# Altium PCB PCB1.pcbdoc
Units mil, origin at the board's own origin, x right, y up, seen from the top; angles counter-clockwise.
Board outline 3435 x 2745 mil, 2 copper layers (Top Layer, Bottom Layer); 19 components, 27 nets, 114 pads, 124 vias.
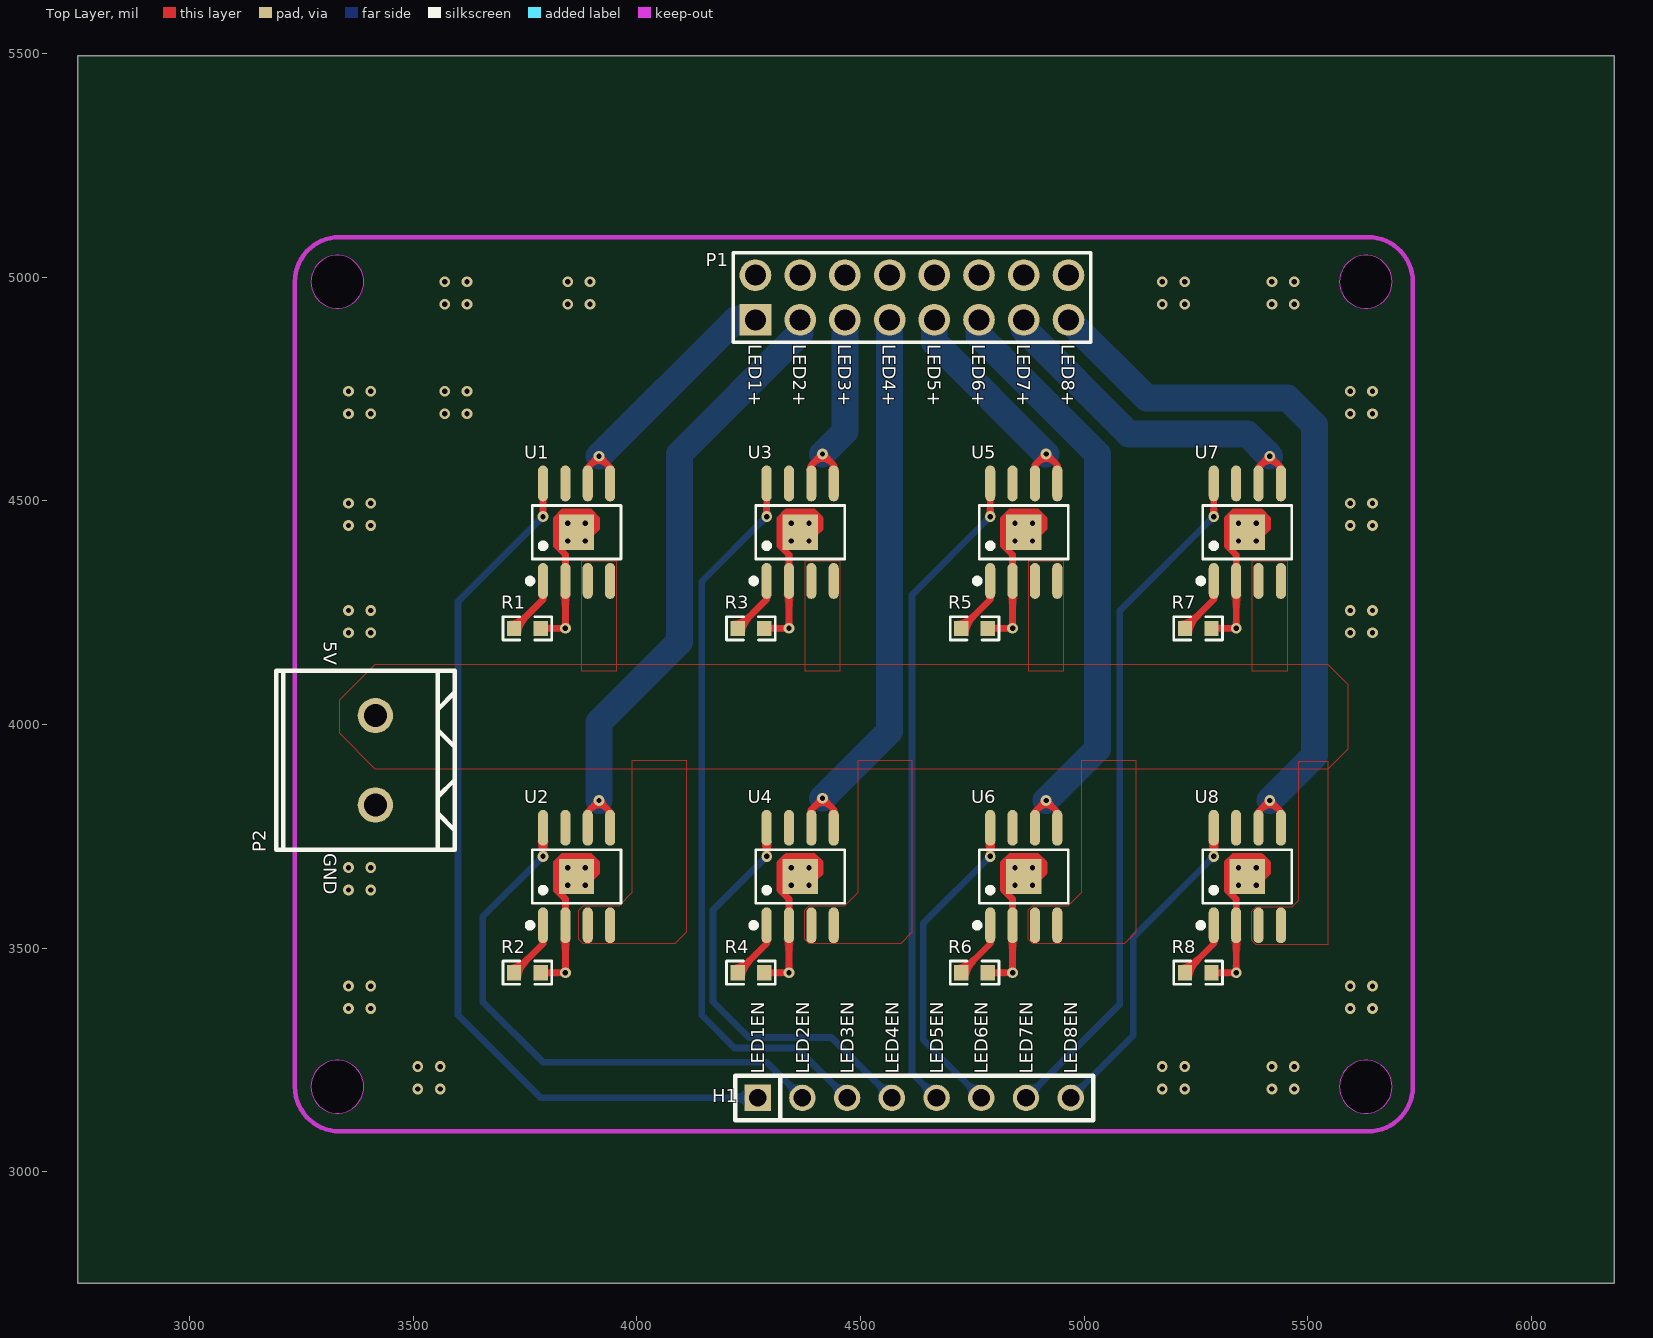
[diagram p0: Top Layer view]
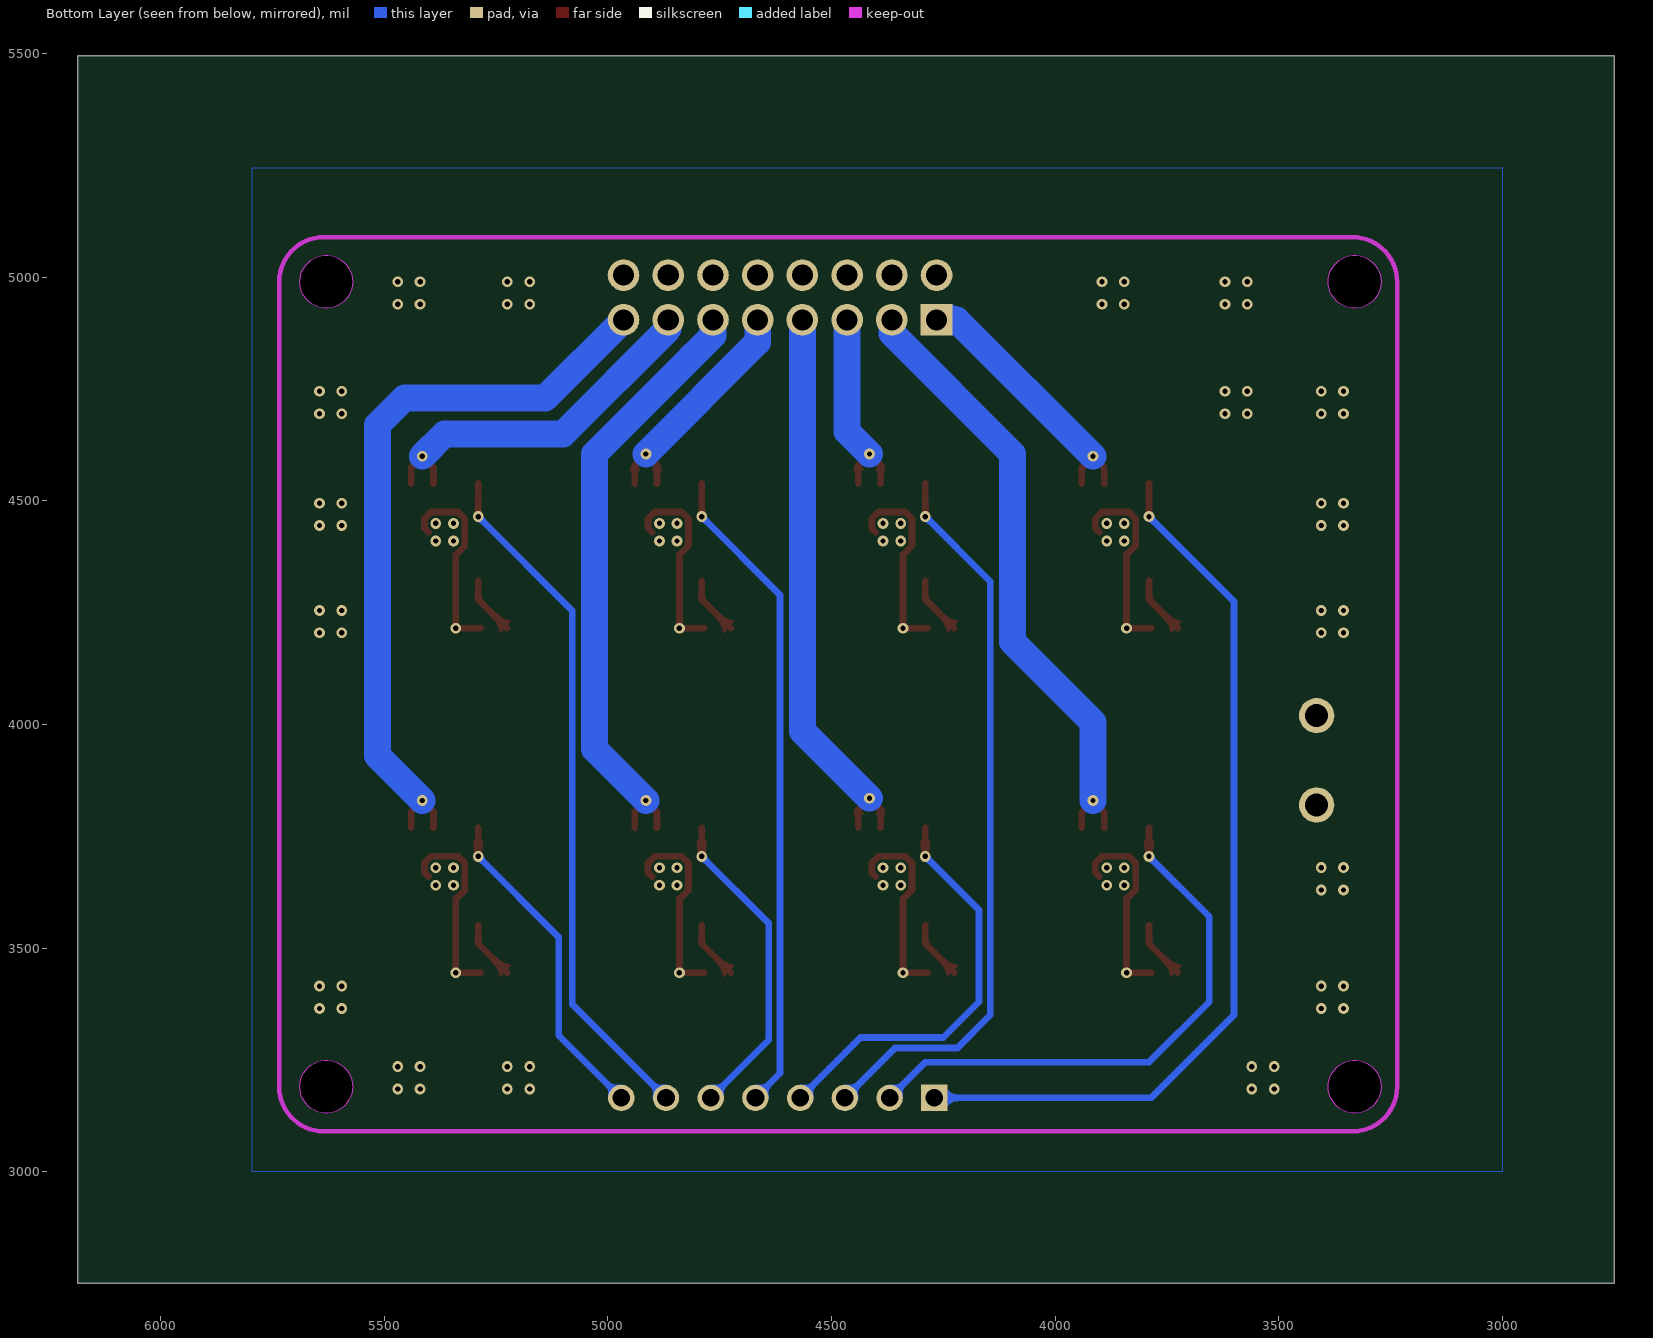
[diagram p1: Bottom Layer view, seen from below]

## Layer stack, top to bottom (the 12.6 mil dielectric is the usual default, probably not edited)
Top Layer: signal copper (thickness not stored)
Dielectric: dielectric 12.6, FR-4, Dk 4.8
Bottom Layer: signal copper (thickness not stored)

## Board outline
6185,2750 2750,2750 2750,5495 6185,5495
cut-out: 3389.06,4990 ccw(c3330,4990) 3270.94,4990 ccw(c3330,4990)
cut-out: 5689.06,4990 ccw(c5630,4990) 5570.94,4990 ccw(c5630,4990)
cut-out: 3389.06,3190 ccw(c3330,3190) 3270.94,3190 ccw(c3330,3190)
cut-out: 5689.06,3190 ccw(c5630,3190) 5570.94,3190 ccw(c5630,3190)

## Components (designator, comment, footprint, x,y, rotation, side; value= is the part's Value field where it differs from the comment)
H1 "PZ254V-11-08P" HDR-TH_8P-P2.54-V-M 4620,3165 r0 top
P1 "2.54-2*8P针_C68234" HDR-TH_16P-P2.54-V-M-R2-C8-S2.54 4615,4955 r0 top
P2 "WJ500V-5.08-2P" CONN-TH_2P-P5.00_WJ500V-5.08-2P 3415,3920 r90 top
R1 "CR0603J1K20P05Z" R0603 3755,4215 r0 top
R2 "CR0603J1K20P05Z" R0603 3755,3445 r0 top
R3 "CR0603J1K20P05Z" R0603 4255,4215 r0 top
R4 "CR0603J1K20P05Z" R0603 4255,3445 r0 top
R5 "CR0603J1K20P05Z" R0603 4755,4215 r0 top
R6 "CR0603J1K20P05Z" R0603 4755,3445 r0 top
R7 "CR0603J1K20P05Z" R0603 5255,4215 r0 top
R8 "CR0603J1K20P05Z" R0603 5255,3445 r0 top
U1 "CN5711" SOIC-8_L5.0-W4.0-P1.27-LS6.0-BL-EP2.0 3865,4430 r0 top
U2 "CN5711" SOIC-8_L5.0-W4.0-P1.27-LS6.0-BL-EP2.0 3865,3660 r0 top
U3 "CN5711" SOIC-8_L5.0-W4.0-P1.27-LS6.0-BL-EP2.0 4365,4430 r0 top
U4 "CN5711" SOIC-8_L5.0-W4.0-P1.27-LS6.0-BL-EP2.0 4365,3660 r0 top
U5 "CN5711" SOIC-8_L5.0-W4.0-P1.27-LS6.0-BL-EP2.0 4865,4430 r0 top
U6 "CN5711" SOIC-8_L5.0-W4.0-P1.27-LS6.0-BL-EP2.0 4865,3660 r0 top
U7 "CN5711" SOIC-8_L5.0-W4.0-P1.27-LS6.0-BL-EP2.0 5365,4430 r0 top
U8 "CN5711" SOIC-8_L5.0-W4.0-P1.27-LS6.0-BL-EP2.0 5365,3660 r0 top

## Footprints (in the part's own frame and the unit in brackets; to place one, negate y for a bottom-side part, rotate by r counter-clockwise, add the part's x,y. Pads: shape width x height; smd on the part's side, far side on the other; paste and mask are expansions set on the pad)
CONN-TH_2P-P5.00_WJ500V-5.08-2P [mm]
  round 2 hole 1.3: 1(-2.54,0) 2(2.54,0)
  silkscreen extent -5.08,-4.52 5.08,5.64
HDR-TH_8P-P2.54-V-M [mm]
  rect 1.5x1.5 hole 1: 1(-8.89,0)
  round 1.5 hole 1: 2(-6.35,0) 3(-3.81,0) 4(-1.27,0) 5(1.27,0) 6(3.81,0) 7(6.35,0) 8(8.89,0)
  silkscreen extent -10.16,-1.27 10.16,1.27
HDR-TH_16P-P2.54-V-M-R2-C8-S2.54 [mm]
  rect 1.8x1.8 hole 1.2: 1(-8.89,-1.27)
  round 1.8 hole 1.2: 2(-8.89,1.27) 3(-6.35,-1.27) 4(-6.35,1.27) 5(-3.81,-1.27) 6(-3.81,1.27) 7(-1.27,-1.27) 8(-1.27,1.27) 9(1.27,-1.27) 10(1.27,1.27) 11(3.81,-1.27) 12(3.81,1.27) 13(6.35,-1.27) 14(6.35,1.27) 15(8.89,-1.27) 16(8.89,1.27)
  silkscreen extent -10.16,-2.54 10.16,2.54
R0603 [mil]
  rect 31.75x34.02 smd: 1(-29.66,0) 2(29.66,0)
  silkscreen extent -55,-26 55,26
SOIC-8_L5.0-W4.0-P1.27-LS6.0-BL-EP2.0 [mm]
  oval 0.574x2.038 smd: 1(-1.905,-2.769) 2(-0.635,-2.769) 3(0.635,-2.769) 4(1.905,-2.769) 5(1.905,2.769) 6(0.635,2.769) 7(-0.635,2.769) 8(-1.905,2.769)
  rect 2x2 smd: 9(0,0)
  silkscreen extent -2.79,-2.92 2.53,1.52

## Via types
v1: diameter 24, hole 12, Top Layer to Bottom Layer, 100 vias
v2: diameter 24.02, hole 12.01, Top Layer to Bottom Layer, 24 vias

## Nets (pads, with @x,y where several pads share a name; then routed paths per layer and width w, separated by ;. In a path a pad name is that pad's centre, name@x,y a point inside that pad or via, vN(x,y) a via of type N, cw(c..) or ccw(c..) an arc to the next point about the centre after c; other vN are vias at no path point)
$1N268: R1.1 U1.1 | length 132.8
  Top Layer w15: R1.1 3790,4279.66 U1.1
$1N528: R2.1 U2.1 | length 132.8
  Top Layer w15: R2.1 3790,3509.66 U2.1
$1N805: R3.1 U3.1 | length 132.8
  Top Layer w15: R3.1 4290,4279.66 U3.1
$1N821: R4.1 U4.1 | length 132.8
  Top Layer w15: R4.1 4290,3509.66 U4.1
$1N1359: R5.1 U5.1 | length 132.8
  Top Layer w15: R5.1 4790,4279.66 U5.1
$1N1375: R6.1 U6.1 | length 132.8
  Top Layer w15: R6.1 4790,3509.66 U6.1
$1N1391: R7.1 U7.1 | length 132.8
  Top Layer w15: R7.1 5290,4279.66 U7.1
$1N1407: R8.1 U8.1 | length 132.8
  Top Layer w15: R8.1 5290,3509.66 U8.1
+5V: P2.2 U1.3 U1.4 U2.3 U2.4 U3.3 U3.4 U4.3 U4.4 U5.3 U5.4 U6.3 U6.4 U7.3 U7.4 U8.3 U8.4
GND: P1.2 P1.4 P1.6 P1.8 P1.10 P1.12 P1.14 P1.16 P2.1 R1.2 R2.2 R3.2 R4.2 R5.2 R6.2 R7.2 R8.2 U1.2 U1.9 U2.2 U2.9 U3.2 U3.9 U4.2 U4.9 U5.2 U5.9 U6.2 U6.9 U7.2 U7.9 U8.2 U8.9 | length 3566.6
  Top Layer w15: R2.2 v2(3840,3445) U2.2 3840,3609.57 3819.82,3629.75 3819.82,3690.25 3834.75,3705.18 3895.25,3705.18 3910.18,3690.25 3910.18,3669.12 U2.9@3900.99,3659.92 ; R1.2 v2(3840,4215) U1.2 3840,4379.57 3819.82,4399.75 3819.82,4460.25 3834.75,4475.19 3895.25,4475.19 3910.18,4460.25 3910.18,4439.12 U1.9@3900.99,4429.92 ; R4.2 v2(4340,3445) U4.2 4340,3609.57 4319.81,3629.75 4319.81,3690.25 4334.75,3705.18 4395.25,3705.18 4410.19,3690.25 4410.19,3669.12 U4.9@4400.99,3659.92 ; R3.2 v2(4340,4215) U3.2 4340,4379.57 4319.81,4399.75 4319.81,4460.25 4334.75,4475.19 4395.25,4475.19 4410.19,4460.25 4410.19,4439.12 U3.9@4400.99,4429.92 ; R6.2 v2(4840,3445) U6.2 4840,3609.57 4819.81,3629.75 4819.81,3690.25 4834.75,3705.18 4895.25,3705.18 4910.19,3690.25 4910.19,3669.12 U6.9@4900.99,3659.92 ; R5.2 v2(4840,4215) U5.2 4840,4379.57 4819.81,4399.75 4819.81,4460.25 4834.75,4475.19 4895.25,4475.19 4910.19,4460.25 4910.19,4439.12 U5.9@4900.99,4429.92 ; R8.2 v2(5340,3445) U8.2 5340,3609.57 5319.81,3629.75 5319.81,3690.25 5334.75,3705.18 5395.25,3705.18 5410.19,3690.25 5410.19,3669.12 U8.9@5400.99,3659.92 ; R7.2 v2(5340,4215) U7.2 5340,4379.57 5319.81,4399.75 5319.81,4460.25 5334.75,4475.19 5395.25,4475.19 5410.19,4460.25 5410.19,4439.12 U7.9@5400.99,4429.92
  other v1: 3510,3185 3560,3185 5175,3185 5225,3185 5420,3185 5470,3185 3510,3235 3560,3235 5175,3235 5225,3235 5420,3235 5470,3235 3355,3365 3405,3365 5595,3365 5645,3365 3355,3415 3405,3415 5595,3415 5645,3415 3355,3630 3405,3630 3355,3680 3405,3680 3355,4205 3405,4205 5595,4205 5645,4205 3355,4255 3405,4255 5595,4255 5645,4255 3355,4445 3405,4445 5595,4445 5645,4445 3355,4495 3405,4495 5595,4495 5645,4495 3355,4695 3405,4695 3570,4695 3620,4695 5595,4695 5645,4695 3355,4745 3405,4745 3570,4745 3620,4745 5595,4745 5645,4745 3570,4940 3620,4940 3845,4940 3895,4940 5175,4940 5225,4940 5420,4940 5470,4940 3570,4990 3620,4990 3845,4990 3895,4990 5175,4990 5225,4990 5420,4990 5470,4990
LED1+: P1.1 U1.5 U1.6 | length 619
  Top Layer w15: U1.6 3890,4575 v2(3915,4600) 3940,4575 U1.5
  Bottom Layer w60: v2(3915,4600) 4220,4905 P1.1
LED1EN: H1.1 U1.8 | length 2014.4
  Top Layer w15: v2(3790,4465) U1.8
  Bottom Layer w15: v2(3790,4465) 3600,4275 3600,3350 3785,3165 H1.1
LED2+: P1.3 U2.5 U2.6 | length 1404.1
  Top Layer w15: U2.6 3890,3805 v2(3915,3830) 3940,3805 U2.5
  Bottom Layer w60: v2(3915,3830) 3915,4005 4095,4185 4095,4605 4365,4875 P1.3
LED2EN: H1.2 U2.8 | length 1249
  Top Layer w15: v2(3790,3705) U2.8
  Bottom Layer w15: v2(3790,3705) 3655,3570 3655,3380 3790,3245 4290,3245 H1.2
LED3+: P1.5 U3.5 U3.6 | length 473.4
  Top Layer w15: U3.6 4390,4580 v2(4415,4605) 4440,4580 U3.5
  Bottom Layer w60: v2(4415,4605) 4465,4655 P1.5
LED3EN: H1.3 U3.8 | length 1650.7
  Top Layer w15: v2(4290,4465) U3.8
  Bottom Layer w15: v2(4290,4465) 4145,4320 4145,3350 4218.33,3276.67 4358.33,3276.67 H1.3
LED4+: P1.7 U4.5 U4.6 | length 1284.8
  Top Layer w15: U4.6 4390,3810 v2(4415,3835) 4440,3810 U4.5
  Bottom Layer w60: v2(4415,3835) 4565,3985 P1.7
LED4EN: H1.4 U4.8 | length 927.8
  Top Layer w15: v2(4290,3705) U4.8
  Bottom Layer w15: v2(4290,3705) 4170,3585 4170,3380 4250,3300 4435,3300 H1.4
LED5+: P1.9 U5.5 U5.6 | length 556.2
  Top Layer w15: U5.6 4890,4580 v2(4915,4605) 4940,4580 U5.5
  Bottom Layer w60: P1.9 4665,4855 v2(4915,4605)
LED5EN: H1.5 U5.8 | length 1469.3
  Top Layer w15: v2(4790,4465) U5.8
  Bottom Layer w15: H1.5 4615,3220 4615,4290 v2(4790,4465)
LED6+: P1.11 U6.5 U6.6 | length 1375.1
  Top Layer w15: U6.6 4890,3805 v2(4915,3830) 4940,3805 U6.5
  Bottom Layer w60: P1.11 4765,4870 5030,4605 5030,3945 v2(4915,3830)
LED6EN: H1.6 U6.8 | length 720
  Top Layer w15: v2(4790,3705) U6.8
  Bottom Layer w15: H1.6 4640,3295 4640,3555 v2(4790,3705)
LED7+: P1.13 U7.5 U7.6 | length 830.7
  Top Layer w15: U7.6 5390,4575 v2(5415,4600) 5440,4575 U7.5
  Bottom Layer w60: P1.13 4865,4885 5100,4650 5365,4650 v2(5415,4600)
LED7EN: H1.7 U7.8 | length 1548
  Top Layer w15: v2(5290,4465) U7.8
  Bottom Layer w15: H1.7 5080,3375 5080,4255 v2(5290,4465)
LED8+: P1.15 U8.5 U8.6 | length 1671.4
  Top Layer w15: U8.6 5390,3805 v2(5415,3830) 5440,3805 U8.5
  Bottom Layer w60: P1.15 5140,4730 5455,4730 5515,4670 5515,3930 v2(5415,3830)
LED8EN: H1.8 U8.8 | length 736.6
  Top Layer w15: v2(5290,3705) U8.8
  Bottom Layer w15: H1.8 5110,3305 5110,3525 v2(5290,3705)
"": U1.7 U2.7 U3.7 U4.7 U5.7 U6.7 U7.7 U8.7
  other v1: 3845.32,3640.32 3884.68,3640.32 4345.31,3640.32 4384.69,3640.32 4845.31,3640.32 4884.69,3640.32 5345.31,3640.32 5384.69,3640.32 3845.32,3679.68 3884.68,3679.68 4345.31,3679.68 4384.69,3679.68 4845.31,3679.68 4884.69,3679.68 5345.31,3679.68 5384.69,3679.68 3845.32,4410.31 3884.68,4410.31 4345.31,4410.31 4384.69,4410.31 4845.31,4410.31 4884.69,4410.31 5345.31,4410.31 5384.69,4410.31 3845.32,4449.69 3884.68,4449.69 4345.31,4449.69 4384.69,4449.69 4845.31,4449.69 4884.69,4449.69 5345.31,4449.69 5384.69,4449.69

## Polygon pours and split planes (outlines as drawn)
+5V on Top Layer (solid, remove dead copper, pour order 1): 3875,4120 3955,4120 3955,4365 3875,4365
+5V on Top Layer (solid, remove dead copper, pour order 2): 4375,4120 4455,4120 4455,4365 4375,4365
+5V on Top Layer (solid, remove dead copper, pour order 3): 4875,4120 4955,4120 4955,4365 4875,4365
+5V on Top Layer (solid, remove dead copper, pour order 4): 5375,4120 5455,4120 5455,4365 5375,4365
GND on Bottom Layer (solid, remove dead copper, pour order 7): 3000,3000 5795,3000 5795,5245 3000,5245
GND on Top Layer (solid, remove dead copper, pour order 10): 3205,3050 5935,3050 5935,5110 3205,5110
+5V on Top Layer (solid, remove dead copper, pour order 0): 3335,4055 3415,4135 5545,4135 5590,4090 5590,3945 5545,3900 3415,3900 3335,3980
+5V on Top Layer (solid, remove dead copper, pour order 5): 3870,3585 3880,3595 3960,3595 3990,3625 3990,3920 4110,3920 4110,3535 4085,3510 3880,3510 3870,3520
+5V on Top Layer (solid, remove dead copper, pour order 6): 5375,3582.5 5385,3592.5 5465,3592.5 5480,3607.5 5480,3917.5 5545,3917.5 5545,3507.5 5385,3507.5 5375,3517.5
+5V on Top Layer (solid, remove dead copper, pour order 8): 4375,3585 4385,3595 4465,3595 4495,3625 4495,3920 4615,3920 4615,3535 4590,3510 4385,3510 4375,3520
+5V on Top Layer (solid, remove dead copper, pour order 9): 4875,3585 4885,3595 4965,3595 4995,3625 4995,3920 5115,3920 5115,3535 5090,3510 4885,3510 4875,3520

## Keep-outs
Board Outline Layer:
  lines w10 net "": 3235,3190 ccw(c3335,3190) 3335,3090 5635,3090 ccw(c5635,3190) 5735,3190 5735,4990 ccw(c5635,4990) 5635,5090 3335,5090 ccw(c3335,4990) 3235,4990 3235,3190
Multi-Layer:
  region net "": 3389.06,4990 ccw(c3330,4990) 3270.94,4990 ccw(c3330,4990)
  region net "": 5689.06,4990 ccw(c5630,4990) 5570.94,4990 ccw(c5630,4990)
  region net "": 3389.06,3190 ccw(c3330,3190) 3270.94,3190 ccw(c3330,3190)
  region net "": 5689.06,3190 ccw(c5630,3190) 5570.94,3190 ccw(c5630,3190)

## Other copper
Top Layer:
  region net $1N268: 3782.5,4279.66 3797.5,4279.66 3797.52,4280.37 3797.59,4281.13 3797.72,4281.9 3797.88,4282.68 3798.11,4283.45 3798.38,4284.17 3798.7,4284.85 3799.08,4285.44 3780.92,4285.44 3781.3,4284.85 3781.62,4284.17 3781.89,4283.45 3782.12,4282.68 3782.28,4281.9 3782.41,4281.13 3782.48,4280.37
  region net LED1EN: 3782.5,4479.25 3797.5,4479.25 3797.45,4481.24 3797.25,4483.54 3796.89,4486.05 3795.97,4491.17 3795.79,4492.51 3795.71,4493.5 3795.69,4494.49 3795.73,4495.48 3795.8,4496.15 3795.91,4496.82 3796.06,4497.5 3796.26,4498.19 3796.5,4498.89 3796.79,4499.61 3797.13,4500.34 3797.75,4501.48 3798.5,4502.66 3799.08,4503.48 3780.92,4503.48 3781.77,4502.26 3782.47,4501.09 3783.05,4499.97 3783.37,4499.25 3783.63,4498.54 3783.85,4497.84 3784.02,4497.16 3784.15,4496.48 3784.24,4495.82 3784.29,4495.15 3784.31,4494.16 3784.27,4493.17 3784.13,4491.84 3783.6,4488.71 3782.86,4484.41 3782.62,4482.19 3782.51,4480.27
  region net $1N528: 3782.5,3509.66 3797.5,3509.66 3797.52,3510.37 3797.59,3511.13 3797.72,3511.9 3797.88,3512.68 3798.11,3513.45 3798.38,3514.17 3798.7,3514.85 3799.08,3515.44 3780.92,3515.44 3781.3,3514.85 3781.62,3514.17 3781.89,3513.45 3782.12,3512.68 3782.28,3511.9 3782.41,3511.13 3782.48,3510.37
  region net LED2EN: 3782.5,3709.25 3797.5,3709.25 3801.14,3738.62 3801.3,3740.2 3778.7,3740.2 3782.34,3710.83
  region net $1N805: 4282.5,4279.66 4297.5,4279.66 4297.52,4280.37 4297.59,4281.13 4297.72,4281.9 4297.88,4282.68 4298.11,4283.45 4298.38,4284.17 4298.7,4284.85 4299.08,4285.44 4280.92,4285.44 4281.3,4284.85 4281.62,4284.17 4281.89,4283.45 4282.12,4282.68 4282.28,4281.9 4282.41,4281.13 4282.48,4280.37
  region net LED3EN: 4282.5,4479.25 4297.5,4479.25 4297.45,4481.24 4297.25,4483.54 4296.89,4486.05 4295.97,4491.17 4295.79,4492.51 4295.71,4493.5 4295.69,4494.49 4295.73,4495.48 4295.8,4496.15 4295.91,4496.82 4296.06,4497.5 4296.26,4498.19 4296.5,4498.89 4296.79,4499.61 4297.13,4500.34 4297.75,4501.48 4298.5,4502.66 4299.08,4503.48 4280.92,4503.48 4281.77,4502.26 4282.48,4501.09 4283.05,4499.97 4283.37,4499.25 4283.63,4498.54 4283.85,4497.84 4284.02,4497.16 4284.15,4496.48 4284.24,4495.82 4284.29,4495.15 4284.31,4494.16 4284.27,4493.17 4284.13,4491.84 4283.6,4488.71 4282.86,4484.41 4282.62,4482.19 4282.51,4480.27
  region net LED3+: 4397.5,4580 4382.5,4580 4382.34,4579.23 4379.29,4570.02 4378.86,4568.61 4378.7,4567.84 4401.3,4567.84 4401.14,4568.61 4398.09,4577.82 4397.66,4579.23
  region net LED3+: 4447.5,4580 4432.5,4580 4432.34,4579.23 4429.29,4570.02 4428.86,4568.61 4428.7,4567.84 4451.3,4567.84 4451.14,4568.61 4448.09,4577.82 4447.66,4579.23
  region net $1N821: 4282.5,3509.66 4297.5,3509.66 4297.52,3510.37 4297.59,3511.13 4297.72,3511.9 4297.88,3512.68 4298.11,3513.45 4298.38,3514.17 4298.7,3514.85 4299.08,3515.44 4280.92,3515.44 4281.3,3514.85 4281.62,3514.17 4281.89,3513.45 4282.12,3512.68 4282.28,3511.9 4282.41,3511.13 4282.48,3510.37
  region net LED4EN: 4282.5,3709.25 4297.5,3709.25 4301.14,3738.62 4301.3,3740.2 4278.7,3740.2 4282.34,3710.83
  region net LED4+: 4397.5,3810 4382.5,3810 4382.34,3809.23 4379.29,3800.02 4378.86,3798.61 4378.7,3797.84 4401.3,3797.84 4401.14,3798.61 4398.09,3807.82 4397.66,3809.23
  region net LED4+: 4447.5,3810 4432.5,3810 4432.34,3809.23 4429.29,3800.02 4428.86,3798.61 4428.7,3797.84 4451.3,3797.84 4451.14,3798.61 4448.09,3807.82 4447.66,3809.23
  region net $1N1359: 4782.5,4279.66 4797.5,4279.66 4797.52,4280.37 4797.59,4281.13 4797.72,4281.9 4797.88,4282.68 4798.11,4283.45 4798.38,4284.17 4798.7,4284.85 4799.08,4285.44 4780.92,4285.44 4781.3,4284.85 4781.62,4284.17 4781.89,4283.45 4782.12,4282.68 4782.28,4281.9 4782.41,4281.13 4782.48,4280.37
  region net LED5EN: 4782.5,4479.25 4797.5,4479.25 4797.45,4481.24 4797.25,4483.54 4796.89,4486.05 4795.97,4491.17 4795.79,4492.51 4795.71,4493.5 4795.69,4494.49 4795.73,4495.48 4795.8,4496.15 4795.91,4496.82 4796.06,4497.5 4796.26,4498.19 4796.5,4498.89 4796.79,4499.61 4797.13,4500.34 4797.75,4501.48 4798.5,4502.66 4799.08,4503.48 4780.92,4503.48 4781.77,4502.26 4782.48,4501.09 4783.05,4499.97 4783.37,4499.25 4783.63,4498.54 4783.85,4497.84 4784.02,4497.16 4784.15,4496.48 4784.24,4495.82 4784.29,4495.15 4784.31,4494.16 4784.27,4493.17 4784.13,4491.84 4783.6,4488.71 4782.86,4484.41 4782.62,4482.19 4782.51,4480.27
  region net LED5+: 4897.5,4580 4882.5,4580 4882.34,4579.23 4879.29,4570.02 4878.86,4568.61 4878.7,4567.84 4901.3,4567.84 4901.14,4568.61 4898.09,4577.82 4897.66,4579.23
  region net LED5+: 4947.5,4580 4932.5,4580 4932.34,4579.23 4929.29,4570.02 4928.86,4568.61 4928.7,4567.84 4951.3,4567.84 4951.14,4568.61 4948.09,4577.82 4947.66,4579.23
  region net $1N1375: 4782.5,3509.66 4797.5,3509.66 4797.52,3510.37 4797.59,3511.13 4797.72,3511.9 4797.88,3512.68 4798.11,3513.45 4798.38,3514.17 4798.7,3514.85 4799.08,3515.44 4780.92,3515.44 4781.3,3514.85 4781.62,3514.17 4781.89,3513.45 4782.12,3512.68 4782.28,3511.9 4782.41,3511.13 4782.48,3510.37
  region net LED6EN: 4782.5,3709.25 4797.5,3709.25 4801.14,3738.62 4801.3,3740.2 4778.7,3740.2 4782.34,3710.83
  region net $1N1391: 5282.5,4279.66 5297.5,4279.66 5297.52,4280.37 5297.59,4281.13 5297.72,4281.9 5297.88,4282.68 5298.11,4283.45 5298.38,4284.17 5298.7,4284.85 5299.08,4285.44 5280.92,4285.44 5281.3,4284.85 5281.62,4284.17 5281.89,4283.45 5282.12,4282.68 5282.28,4281.9 5282.41,4281.13 5282.48,4280.37
  region net LED7EN: 5282.5,4479.25 5297.5,4479.25 5297.45,4481.24 5297.25,4483.54 5296.89,4486.05 5295.97,4491.17 5295.79,4492.51 5295.71,4493.5 5295.69,4494.49 5295.73,4495.48 5295.8,4496.15 5295.91,4496.82 5296.06,4497.5 5296.26,4498.19 5296.5,4498.89 5296.79,4499.61 5297.13,4500.34 5297.75,4501.48 5298.5,4502.66 5299.08,4503.48 5280.92,4503.48 5281.77,4502.26 5282.48,4501.09 5283.05,4499.97 5283.37,4499.25 5283.63,4498.54 5283.85,4497.84 5284.02,4497.16 5284.15,4496.48 5284.24,4495.82 5284.29,4495.15 5284.31,4494.16 5284.27,4493.17 5284.13,4491.84 5283.6,4488.71 5282.86,4484.41 5282.62,4482.19 5282.51,4480.27
  region net $1N1407: 5282.5,3509.66 5297.5,3509.66 5297.52,3510.37 5297.59,3511.13 5297.72,3511.9 5297.88,3512.68 5298.11,3513.45 5298.38,3514.17 5298.7,3514.85 5299.08,3515.44 5280.92,3515.44 5281.3,3514.85 5281.62,3514.17 5281.89,3513.45 5282.12,3512.68 5282.28,3511.9 5282.41,3511.13 5282.48,3510.37
  region net LED8EN: 5282.5,3709.25 5297.5,3709.25 5301.14,3738.62 5301.3,3740.2 5278.7,3740.2 5282.34,3710.83
  region net $1N268: 3757.13,4236.18 3747.65,4247.92 cw(c3707.88,4287.69) 3715.83,4232.01 3741.22,4204.36 cw(c3796.9,4196.4)
  region net $1N528: 3757.13,3466.18 3747.65,3477.92 cw(c3707.88,3517.69) 3715.83,3462.01 3741.22,3434.36 cw(c3796.9,3426.4)
  region net $1N805: 4257.13,4236.18 4247.65,4247.92 cw(c4207.88,4287.69) 4215.83,4232.01 4241.22,4204.36 cw(c4296.9,4196.4)
  region net $1N821: 4257.13,3466.18 4247.65,3477.92 cw(c4207.88,3517.69) 4215.83,3462.01 4241.22,3434.36 cw(c4296.9,3426.4)
  region net $1N1359: 4757.13,4236.18 4747.65,4247.92 cw(c4707.88,4287.69) 4715.83,4232.01 4741.22,4204.36 cw(c4796.9,4196.4)
  region net $1N1375: 4757.13,3466.18 4747.65,3477.92 cw(c4707.88,3517.69) 4715.83,3462.01 4741.22,3434.36 cw(c4796.9,3426.4)
  region net $1N1391: 5257.13,4236.18 5247.65,4247.92 cw(c5207.88,4287.69) 5215.83,4232.01 5241.22,4204.36 cw(c5296.9,4196.4)
  region net $1N1407: 5257.13,3466.18 5247.65,3477.92 cw(c5207.88,3517.69) 5215.83,3462.01 5241.22,3434.36 cw(c5296.9,3426.4)
  region net LED1+: 3898.14,4593.74 3908.74,4583.14 3910.75,4585.28 3911.5,4586.04 3911.88,4586.39 3912.28,4586.71 3912.69,4587 3913.12,4587.27 3913.58,4587.5 3914.07,4587.69 3914.59,4587.84 3915.15,4587.95 3915.75,4588.02 3903.02,4600.75 3902.95,4600.15 3902.84,4599.59 3902.69,4599.07 3902.5,4598.58 3902.27,4598.12 3902,4597.69 3901.71,4597.28 3901.39,4596.88 3900.67,4596.12 3898.58,4594.18
  region net LED1+: 3921.26,4583.14 3931.86,4593.74 3929.72,4595.75 3928.96,4596.5 3928.61,4596.88 3928.29,4597.28 3928,4597.69 3927.73,4598.12 3927.5,4598.58 3927.31,4599.07 3927.16,4599.59 3927.05,4600.15 3926.98,4600.75 3914.25,4588.02 3914.85,4587.95 3915.41,4587.84 3915.93,4587.69 3916.42,4587.5 3916.88,4587.27 3917.31,4587 3917.72,4586.71 3918.12,4586.39 3918.88,4585.67 3920.82,4583.58
  region net LED2+: 3898.14,3823.74 3908.74,3813.14 3910.75,3815.28 3911.5,3816.04 3911.88,3816.39 3912.28,3816.71 3912.69,3817 3913.12,3817.27 3913.58,3817.5 3914.07,3817.69 3914.59,3817.84 3915.15,3817.95 3915.75,3818.02 3903.02,3830.75 3902.95,3830.15 3902.84,3829.59 3902.69,3829.07 3902.5,3828.58 3902.27,3828.12 3902,3827.69 3901.71,3827.28 3901.39,3826.88 3900.67,3826.12 3898.58,3824.18
  region net LED2+: 3921.26,3813.14 3931.86,3823.74 3929.72,3825.75 3928.96,3826.5 3928.61,3826.88 3928.29,3827.28 3928,3827.69 3927.73,3828.12 3927.5,3828.58 3927.31,3829.07 3927.16,3829.59 3927.05,3830.15 3926.98,3830.75 3914.25,3818.02 3914.85,3817.95 3915.41,3817.84 3915.93,3817.69 3916.42,3817.5 3916.88,3817.27 3917.31,3817 3917.72,3816.71 3918.12,3816.39 3918.88,3815.67 3920.82,3813.58
  region net LED1EN: 3797.5,4481.35 3782.5,4481.35 3782.6,4478.42 3782.6,4477.35 3782.58,4476.83 3782.53,4476.32 3782.44,4475.82 3782.32,4475.33 3782.16,4474.84 3781.96,4474.36 3781.69,4473.89 3781.38,4473.41 3780.99,4472.94 3799.01,4472.94 3798.62,4473.41 3798.31,4473.89 3798.04,4474.36 3797.84,4474.84 3797.68,4475.33 3797.56,4475.82 3797.47,4476.32 3797.42,4476.83 3797.39,4477.88 3797.49,4480.73
  region net LED2EN: 3797.5,3721.35 3782.5,3721.35 3782.6,3718.42 3782.6,3717.35 3782.58,3716.83 3782.53,3716.32 3782.44,3715.82 3782.32,3715.33 3782.16,3714.84 3781.96,3714.36 3781.69,3713.89 3781.38,3713.41 3780.99,3712.94 3799.01,3712.94 3798.62,3713.41 3798.31,3713.89 3798.04,3714.36 3797.84,3714.84 3797.68,3715.33 3797.56,3715.82 3797.47,3716.32 3797.42,3716.83 3797.39,3717.88 3797.49,3720.73
  region net LED3+: 4398.14,4598.74 4408.74,4588.14 4410.75,4590.28 4411.5,4591.04 4411.88,4591.39 4412.28,4591.71 4412.69,4592 4413.12,4592.27 4413.58,4592.5 4414.07,4592.69 4414.59,4592.84 4415.15,4592.95 4415.75,4593.02 4403.02,4605.75 4402.95,4605.15 4402.84,4604.59 4402.69,4604.07 4402.5,4603.58 4402.27,4603.12 4402,4602.69 4401.71,4602.28 4401.39,4601.88 4400.67,4601.12 4398.58,4599.18
  region net LED3+: 4421.26,4588.14 4431.86,4598.74 4429.72,4600.75 4428.96,4601.5 4428.61,4601.88 4428.29,4602.28 4428,4602.69 4427.73,4603.12 4427.5,4603.58 4427.31,4604.07 4427.16,4604.59 4427.05,4605.15 4426.98,4605.75 4414.25,4593.02 4414.85,4592.95 4415.41,4592.84 4415.93,4592.69 4416.42,4592.5 4416.88,4592.27 4417.31,4592 4417.72,4591.71 4418.12,4591.39 4418.88,4590.67 4420.82,4588.58
  region net LED4+: 4398.14,3828.74 4408.74,3818.14 4410.75,3820.28 4411.5,3821.04 4411.88,3821.39 4412.28,3821.71 4412.69,3822 4413.12,3822.27 4413.58,3822.5 4414.07,3822.69 4414.59,3822.84 4415.15,3822.95 4415.75,3823.02 4403.02,3835.75 4402.95,3835.15 4402.84,3834.59 4402.69,3834.07 4402.5,3833.58 4402.27,3833.12 4402,3832.69 4401.71,3832.28 4401.39,3831.88 4400.67,3831.12 4398.58,3829.18
  region net LED4+: 4421.26,3818.14 4431.86,3828.74 4429.72,3830.75 4428.96,3831.5 4428.61,3831.88 4428.29,3832.28 4428,3832.69 4427.73,3833.12 4427.5,3833.58 4427.31,3834.07 4427.16,3834.59 4427.05,3835.15 4426.98,3835.75 4414.25,3823.02 4414.85,3822.95 4415.41,3822.84 4415.93,3822.69 4416.42,3822.5 4416.88,3822.27 4417.31,3822 4417.72,3821.71 4418.12,3821.39 4418.88,3820.67 4420.82,3818.58
  region net LED5+: 4898.14,4598.74 4908.74,4588.14 4910.75,4590.28 4911.5,4591.04 4911.88,4591.39 4912.28,4591.71 4912.69,4592 4913.12,4592.27 4913.58,4592.5 4914.07,4592.69 4914.59,4592.84 4915.15,4592.95 4915.75,4593.02 4903.02,4605.75 4902.95,4605.15 4902.84,4604.59 4902.69,4604.07 4902.5,4603.58 4902.27,4603.12 4902,4602.69 4901.71,4602.28 4901.39,4601.88 4900.67,4601.12 4898.58,4599.18
  region net LED5+: 4921.26,4588.14 4931.86,4598.74 4929.72,4600.75 4928.96,4601.5 4928.61,4601.88 4928.29,4602.28 4928,4602.69 4927.73,4603.12 4927.5,4603.58 4927.31,4604.07 4927.16,4604.59 4927.05,4605.15 4926.98,4605.75 4914.25,4593.02 4914.85,4592.95 4915.41,4592.84 4915.93,4592.69 4916.42,4592.5 4916.88,4592.27 4917.31,4592 4917.72,4591.71 4918.12,4591.39 4918.88,4590.67 4920.82,4588.58
  region net LED6+: 4921.26,3813.14 4931.86,3823.74 4929.72,3825.75 4928.96,3826.5 4928.61,3826.88 4928.29,3827.28 4928,3827.69 4927.73,3828.12 4927.5,3828.58 4927.31,3829.07 4927.16,3829.59 4927.05,3830.15 4926.98,3830.75 4914.25,3818.02 4914.85,3817.95 4915.41,3817.84 4915.93,3817.69 4916.42,3817.5 4916.88,3817.27 4917.31,3817 4917.72,3816.71 4918.12,3816.39 4918.88,3815.67 4920.82,3813.58
  region net LED6+: 4898.14,3823.74 4908.74,3813.14 4910.75,3815.28 4911.5,3816.04 4911.88,3816.39 4912.28,3816.71 4912.69,3817 4913.12,3817.27 4913.58,3817.5 4914.07,3817.69 4914.59,3817.84 4915.15,3817.95 4915.75,3818.02 4903.02,3830.75 4902.95,3830.15 4902.84,3829.59 4902.69,3829.07 4902.5,3828.58 4902.27,3828.12 4902,3827.69 4901.71,3827.28 4901.39,3826.88 4900.67,3826.12 4898.58,3824.18
  region net LED7+: 5398.14,4593.74 5408.74,4583.14 5410.75,4585.28 5411.5,4586.04 5411.88,4586.39 5412.28,4586.71 5412.69,4587 5413.12,4587.27 5413.58,4587.5 5414.07,4587.69 5414.59,4587.84 5415.15,4587.95 5415.75,4588.02 5403.02,4600.75 5402.95,4600.15 5402.84,4599.59 5402.69,4599.07 5402.5,4598.58 5402.27,4598.12 5402,4597.69 5401.71,4597.28 5401.39,4596.88 5400.67,4596.12 5398.58,4594.18
  region net LED7+: 5421.26,4583.14 5431.86,4593.74 5429.72,4595.75 5428.96,4596.5 5428.61,4596.88 5428.29,4597.28 5428,4597.69 5427.73,4598.12 5427.5,4598.58 5427.31,4599.07 5427.16,4599.59 5427.05,4600.15 5426.98,4600.75 5414.25,4588.02 5414.85,4587.95 5415.41,4587.84 5415.93,4587.69 5416.42,4587.5 5416.88,4587.27 5417.31,4587 5417.72,4586.71 5418.12,4586.39 5418.88,4585.67 5420.82,4583.58
  region net LED8+: 5398.14,3823.74 5408.74,3813.14 5410.75,3815.28 5411.5,3816.04 5411.88,3816.39 5412.28,3816.71 5412.69,3817 5413.12,3817.27 5413.58,3817.5 5414.07,3817.69 5414.59,3817.84 5415.15,3817.95 5415.75,3818.02 5403.02,3830.75 5402.95,3830.15 5402.84,3829.59 5402.69,3829.07 5402.5,3828.58 5402.27,3828.12 5402,3827.69 5401.71,3827.28 5401.39,3826.88 5400.67,3826.12 5398.58,3824.18
  region net LED8+: 5421.26,3813.14 5431.86,3823.74 5429.72,3825.75 5428.96,3826.5 5428.61,3826.88 5428.29,3827.28 5428,3827.69 5427.73,3828.12 5427.5,3828.58 5427.31,3829.07 5427.16,3829.59 5427.05,3830.15 5426.98,3830.75 5414.25,3818.02 5414.85,3817.95 5415.41,3817.84 5415.93,3817.69 5416.42,3817.5 5416.88,3817.27 5417.31,3817 5417.72,3816.71 5418.12,3816.39 5418.88,3815.67 5420.82,3813.58
  region net LED3EN: 4297.5,4481.35 4282.5,4481.35 4282.6,4478.42 4282.6,4477.35 4282.58,4476.83 4282.53,4476.32 4282.44,4475.82 4282.32,4475.33 4282.16,4474.84 4281.96,4474.36 4281.69,4473.89 4281.38,4473.41 4280.99,4472.94 4299.01,4472.94 4298.62,4473.41 4298.31,4473.89 4298.04,4474.36 4297.84,4474.84 4297.68,4475.33 4297.56,4475.82 4297.47,4476.32 4297.42,4476.83 4297.39,4477.88 4297.49,4480.73
  region net LED4EN: 4297.5,3721.35 4282.5,3721.35 4282.6,3718.42 4282.6,3717.35 4282.58,3716.83 4282.53,3716.32 4282.44,3715.82 4282.32,3715.33 4282.16,3714.84 4281.96,3714.36 4281.69,3713.89 4281.38,3713.41 4280.99,3712.94 4299.01,3712.94 4298.62,3713.41 4298.31,3713.89 4298.04,3714.36 4297.84,3714.84 4297.68,3715.33 4297.56,3715.82 4297.47,3716.32 4297.42,3716.83 4297.39,3717.88 4297.49,3720.73
  region net LED5EN: 4797.5,4481.35 4782.5,4481.35 4782.6,4478.42 4782.6,4477.35 4782.58,4476.83 4782.53,4476.32 4782.44,4475.82 4782.32,4475.33 4782.16,4474.84 4781.96,4474.36 4781.69,4473.89 4781.38,4473.41 4780.99,4472.94 4799.01,4472.94 4798.62,4473.41 4798.31,4473.89 4798.04,4474.36 4797.84,4474.84 4797.68,4475.33 4797.56,4475.82 4797.47,4476.32 4797.42,4476.83 4797.39,4477.88 4797.49,4480.73
  region net LED6EN: 4797.5,3721.35 4782.5,3721.35 4782.6,3718.42 4782.6,3717.35 4782.58,3716.83 4782.53,3716.32 4782.44,3715.82 4782.32,3715.33 4782.16,3714.84 4781.96,3714.36 4781.69,3713.89 4781.38,3713.41 4780.99,3712.94 4799.01,3712.94 4798.62,3713.41 4798.31,3713.89 4798.04,3714.36 4797.84,3714.84 4797.68,3715.33 4797.56,3715.82 4797.47,3716.32 4797.42,3716.83 4797.39,3717.88 4797.49,3720.73
  region net LED7EN: 5297.5,4481.35 5282.5,4481.35 5282.6,4478.42 5282.6,4477.35 5282.58,4476.83 5282.53,4476.32 5282.44,4475.82 5282.32,4475.33 5282.16,4474.84 5281.96,4474.36 5281.69,4473.89 5281.38,4473.41 5280.99,4472.94 5299.01,4472.94 5298.62,4473.41 5298.31,4473.89 5298.04,4474.36 5297.84,4474.84 5297.68,4475.33 5297.56,4475.82 5297.47,4476.32 5297.42,4476.83 5297.39,4477.88 5297.49,4480.73
  region net LED8EN: 5297.5,3721.35 5282.5,3721.35 5282.6,3718.42 5282.6,3717.35 5282.58,3716.83 5282.53,3716.32 5282.44,3715.82 5282.32,3715.33 5282.16,3714.84 5281.96,3714.36 5281.69,3713.89 5281.38,3713.41 5280.99,3712.94 5299.01,3712.94 5298.62,3713.41 5298.31,3713.89 5298.04,3714.36 5297.84,3714.84 5297.68,3715.33 5297.56,3715.82 5297.47,3716.32 5297.42,3716.83 5297.39,3717.88 5297.49,3720.73
  region net LED1+: 3904.39,4578.79 3904.91,4579.27 3905.45,4579.72 3906.02,4580.14 3906.61,4580.53 3907.23,4580.88 3907.87,4581.21 3909.2,4581.77 3910.6,4582.2 3912.04,4582.52 3913.51,4582.7 3915,4582.76 3916.49,4582.7 3917.96,4582.52 3919.4,4582.2 3920.8,4581.77 3922.13,4581.21 3922.77,4580.88 3923.39,4580.53 3923.98,4580.14 3924.55,4579.72 3925.09,4579.27 3925.61,4578.79 3936.21,4589.39 3920.3,4594.7 3893.79,4589.39
  region net LED2+: 3904.39,3808.79 3904.91,3809.27 3905.45,3809.72 3906.02,3810.14 3906.61,3810.53 3907.23,3810.88 3907.87,3811.21 3909.2,3811.77 3910.6,3812.2 3912.04,3812.52 3913.51,3812.7 3915,3812.76 3916.49,3812.7 3917.96,3812.52 3919.4,3812.2 3920.8,3811.77 3922.13,3811.21 3922.77,3810.88 3923.39,3810.53 3923.98,3810.14 3924.55,3809.72 3925.09,3809.27 3925.61,3808.79 3936.21,3819.39 3920.3,3824.7 3893.79,3819.39
  region net LED3+: 4404.39,4583.79 4404.91,4584.27 4405.45,4584.72 4406.02,4585.14 4406.61,4585.53 4407.23,4585.88 4407.87,4586.21 4409.2,4586.77 4410.6,4587.2 4412.04,4587.52 4413.51,4587.7 4415,4587.76 4416.49,4587.7 4417.96,4587.52 4419.4,4587.2 4420.8,4586.77 4422.13,4586.21 4422.77,4585.88 4423.39,4585.53 4423.98,4585.14 4424.55,4584.72 4425.09,4584.27 4425.61,4583.79 4436.21,4594.39 4420.3,4599.7 4393.79,4594.39
  region net LED4+: 4404.39,3813.79 4404.91,3814.27 4405.45,3814.72 4406.02,3815.14 4406.61,3815.53 4407.23,3815.88 4407.87,3816.21 4409.2,3816.77 4410.6,3817.2 4412.04,3817.52 4413.51,3817.7 4415,3817.76 4416.49,3817.7 4417.96,3817.52 4419.4,3817.2 4420.8,3816.77 4422.13,3816.21 4422.77,3815.88 4423.39,3815.53 4423.98,3815.14 4424.55,3814.72 4425.09,3814.27 4425.61,3813.79 4436.21,3824.39 4420.3,3829.7 4393.79,3824.39
  region net LED5+: 4904.39,4583.79 4904.91,4584.27 4905.45,4584.72 4906.02,4585.14 4906.61,4585.53 4907.23,4585.88 4907.87,4586.21 4909.2,4586.77 4910.6,4587.2 4912.04,4587.52 4913.51,4587.7 4915,4587.76 4916.49,4587.7 4917.96,4587.52 4919.4,4587.2 4920.8,4586.77 4922.13,4586.21 4922.77,4585.88 4923.39,4585.53 4923.98,4585.14 4924.55,4584.72 4925.09,4584.27 4925.61,4583.79 4936.21,4594.39 4920.3,4599.7 4893.79,4594.39
  region net LED6+: 4904.39,3808.79 4904.91,3809.27 4905.45,3809.72 4906.02,3810.14 4906.61,3810.53 4907.23,3810.88 4907.87,3811.21 4909.2,3811.77 4910.6,3812.2 4912.04,3812.52 4913.51,3812.7 4915,3812.76 4916.49,3812.7 4917.96,3812.52 4919.4,3812.2 4920.8,3811.77 4922.13,3811.21 4922.77,3810.88 4923.39,3810.53 4923.98,3810.14 4924.55,3809.72 4925.09,3809.27 4925.61,3808.79 4936.21,3819.39 4920.3,3824.7 4893.79,3819.39
  region net LED7+: 5404.39,4578.79 5404.91,4579.27 5405.45,4579.72 5406.02,4580.14 5406.61,4580.53 5407.23,4580.88 5407.87,4581.21 5409.2,4581.77 5410.6,4582.2 5412.04,4582.52 5413.51,4582.7 5415,4582.76 5416.49,4582.7 5417.96,4582.52 5419.4,4582.2 5420.8,4581.77 5422.13,4581.21 5422.77,4580.88 5423.39,4580.53 5423.98,4580.14 5424.55,4579.72 5425.09,4579.27 5425.61,4578.79 5436.21,4589.39 5420.3,4594.7 5393.79,4589.39
  region net LED8+: 5404.39,3808.79 5404.91,3809.27 5405.45,3809.72 5406.02,3810.14 5406.61,3810.53 5407.23,3810.88 5407.87,3811.21 5409.2,3811.77 5410.6,3812.2 5412.04,3812.52 5413.51,3812.7 5415,3812.76 5416.49,3812.7 5417.96,3812.52 5419.4,3812.2 5420.8,3811.77 5422.13,3811.21 5422.77,3810.88 5423.39,3810.53 5423.98,3810.14 5424.55,3809.72 5425.09,3809.27 5425.61,3808.79 5436.21,3819.39 5420.3,3824.7 5393.79,3819.39
Bottom Layer:
  region net LED1+: 4220,4935 4220,4875 cw(c4220,4863.55) 4229.57,4869.84 4229.57,4940.16 cw(c4220,4946.45)
  region net LED1EN: 4217.97,3172.5 4217.97,3157.5 cw(c4217.97,3129.38) 4240.47,3146.25 4240.47,3183.75 cw(c4217.97,3200.62)
  region net LED2EN: 4346.88,3198.73 4336.27,3188.12 4337.29,3187.03 4338.17,3185.96 4338.67,3185.25 4339.12,3184.55 4339.51,3183.86 4339.85,3183.16 4340.14,3182.47 4340.39,3181.78 4340.59,3181.09 4340.75,3180.39 4340.93,3179.34 4341.03,3178.28 4341.07,3177.21 4341.04,3175.37 4340.61,3169.76 4340.46,3166.61 4340.48,3164.17 4340.53,3163.15 4371.85,3194.47 4369.35,3194.55 4366.56,3194.47 4360.39,3194 4358.52,3193.93 4357.07,3193.95 4356.01,3194.03 4354.96,3194.18 4354.26,3194.33 4353.57,3194.51 4352.87,3194.73 4352.18,3195 4351.49,3195.31 4350.79,3195.68 4350.1,3196.1 4349.39,3196.57 4348.68,3197.11 4347.61,3198.03
  region net LED3EN: 4446.88,3198.73 4436.27,3188.12 4437.29,3187.03 4438.17,3185.96 4438.67,3185.25 4439.12,3184.55 4439.51,3183.86 4439.85,3183.16 4440.14,3182.47 4440.39,3181.78 4440.59,3181.09 4440.75,3180.39 4440.93,3179.34 4441.03,3178.28 4441.07,3177.21 4441.04,3175.37 4440.61,3169.76 4440.46,3166.61 4440.48,3164.17 4440.53,3163.15 4471.85,3194.47 4469.35,3194.55 4466.56,3194.47 4460.39,3194 4458.52,3193.93 4457.07,3193.95 4456.01,3194.03 4454.96,3194.18 4454.26,3194.33 4453.57,3194.51 4452.87,3194.73 4452.18,3195 4451.49,3195.31 4450.79,3195.68 4450.1,3196.1 4449.39,3196.57 4448.68,3197.11 4447.61,3198.03
  region net LED4EN: 4546.88,3198.73 4536.27,3188.12 4537.29,3187.03 4538.17,3185.96 4538.67,3185.25 4539.12,3184.55 4539.51,3183.86 4539.85,3183.16 4540.14,3182.47 4540.39,3181.78 4540.59,3181.09 4540.75,3180.39 4540.93,3179.34 4541.03,3178.28 4541.07,3177.21 4541.04,3175.37 4540.61,3169.76 4540.46,3166.61 4540.48,3164.17 4540.53,3163.15 4571.85,3194.47 4569.35,3194.55 4566.56,3194.47 4560.39,3194 4558.52,3193.93 4557.07,3193.95 4556.01,3194.03 4554.96,3194.18 4554.26,3194.33 4553.57,3194.51 4552.87,3194.73 4552.18,3195 4551.49,3195.31 4550.79,3195.68 4550.1,3196.1 4549.39,3196.57 4548.68,3197.11 4547.61,3198.03
  region net LED5EN: 4646.88,3198.73 4636.27,3188.12 4637.29,3187.03 4638.17,3185.96 4638.67,3185.25 4639.12,3184.55 4639.51,3183.86 4639.85,3183.16 4640.14,3182.47 4640.39,3181.78 4640.59,3181.09 4640.75,3180.39 4640.93,3179.34 4641.03,3178.28 4641.07,3177.21 4641.04,3175.37 4640.61,3169.76 4640.46,3166.61 4640.48,3164.17 4640.53,3163.15 4671.85,3194.47 4669.35,3194.55 4666.56,3194.47 4660.39,3194 4658.52,3193.93 4657.07,3193.95 4656.01,3194.03 4654.96,3194.18 4654.26,3194.33 4653.57,3194.51 4652.87,3194.73 4652.18,3195 4651.49,3195.31 4650.79,3195.68 4650.1,3196.1 4649.39,3196.57 4648.68,3197.11 4647.61,3198.03
  region net LED6EN: 4746.88,3198.73 4736.27,3188.12 4737.29,3187.03 4738.17,3185.96 4738.67,3185.25 4739.12,3184.55 4739.51,3183.86 4739.85,3183.16 4740.14,3182.47 4740.39,3181.78 4740.59,3181.09 4740.75,3180.39 4740.93,3179.34 4741.03,3178.28 4741.07,3177.21 4741.04,3175.37 4740.61,3169.76 4740.46,3166.61 4740.48,3164.17 4740.53,3163.15 4771.85,3194.47 4769.35,3194.55 4766.56,3194.47 4760.39,3194 4758.52,3193.93 4757.07,3193.95 4756.01,3194.03 4754.96,3194.18 4754.26,3194.33 4753.57,3194.51 4752.87,3194.73 4752.18,3195 4751.49,3195.31 4750.79,3195.68 4750.1,3196.1 4749.39,3196.57 4748.68,3197.11 4747.61,3198.03
  region net LED7EN: 4903.73,3188.12 4893.12,3198.73 4892.03,3197.71 4890.96,3196.83 4890.25,3196.33 4889.55,3195.88 4888.86,3195.49 4888.16,3195.15 4887.47,3194.86 4886.78,3194.61 4886.09,3194.41 4885.39,3194.25 4884.34,3194.07 4883.28,3193.97 4882.21,3193.93 4880.37,3193.96 4874.76,3194.39 4871.61,3194.54 4869.17,3194.52 4868.15,3194.47 4899.47,3163.15 4899.55,3165.65 4899.47,3168.44 4899,3174.61 4898.93,3176.48 4898.95,3177.93 4899.03,3178.99 4899.18,3180.04 4899.33,3180.74 4899.51,3181.43 4899.73,3182.13 4900,3182.82 4900.31,3183.51 4900.68,3184.21 4901.1,3184.9 4901.57,3185.61 4902.11,3186.32 4903.03,3187.39
  region net LED8EN: 5003.73,3188.12 4993.12,3198.73 4992.03,3197.71 4990.96,3196.83 4990.25,3196.33 4989.55,3195.88 4988.86,3195.49 4988.16,3195.15 4987.47,3194.86 4986.78,3194.61 4986.09,3194.41 4985.39,3194.25 4984.34,3194.07 4983.28,3193.97 4982.21,3193.93 4980.37,3193.96 4974.76,3194.39 4971.61,3194.54 4969.17,3194.52 4968.15,3194.47 4999.47,3163.15 4999.55,3165.65 4999.47,3168.44 4999,3174.61 4998.93,3176.48 4998.95,3177.93 4999.03,3178.99 4999.18,3180.04 4999.33,3180.74 4999.51,3181.43 4999.73,3182.13 5000,3182.82 5000.31,3183.51 5000.68,3184.21 5001.1,3184.9 5001.57,3185.61 5002.11,3186.32 5003.03,3187.39
  region net LED1EN: 3773.14,4458.74 3783.74,4448.14 3785.75,4450.28 3786.5,4451.04 3786.88,4451.39 3787.28,4451.71 3787.69,4452 3788.12,4452.27 3788.58,4452.5 3789.07,4452.69 3789.59,4452.84 3790.15,4452.95 3790.75,4453.02 3778.02,4465.75 3777.95,4465.15 3777.84,4464.59 3777.69,4464.07 3777.5,4463.58 3777.27,4463.12 3777,4462.69 3776.71,4462.28 3776.39,4461.88 3775.67,4461.12 3773.58,4459.18
  region net LED2EN: 3773.14,3698.74 3783.74,3688.14 3785.75,3690.28 3786.5,3691.04 3786.88,3691.39 3787.28,3691.71 3787.69,3692 3788.12,3692.27 3788.58,3692.5 3789.07,3692.69 3789.59,3692.84 3790.15,3692.95 3790.75,3693.02 3778.02,3705.75 3777.95,3705.15 3777.84,3704.59 3777.69,3704.07 3777.5,3703.58 3777.27,3703.12 3777,3702.69 3776.71,3702.28 3776.39,3701.88 3775.67,3701.12 3773.58,3699.18
  region net LED3EN: 4273.14,4458.74 4283.74,4448.14 4285.75,4450.28 4286.5,4451.04 4286.88,4451.39 4287.28,4451.71 4287.69,4452 4288.12,4452.27 4288.58,4452.5 4289.07,4452.69 4289.59,4452.84 4290.15,4452.95 4290.75,4453.02 4278.02,4465.75 4277.95,4465.15 4277.84,4464.59 4277.69,4464.07 4277.5,4463.58 4277.27,4463.12 4277,4462.69 4276.71,4462.28 4276.39,4461.88 4275.67,4461.12 4273.58,4459.18
  region net LED4EN: 4273.14,3698.74 4283.74,3688.14 4285.75,3690.28 4286.5,3691.04 4286.88,3691.39 4287.28,3691.71 4287.69,3692 4288.12,3692.27 4288.58,3692.5 4289.07,3692.69 4289.59,3692.84 4290.15,3692.95 4290.75,3693.02 4278.02,3705.75 4277.95,3705.15 4277.84,3704.59 4277.69,3704.07 4277.5,3703.58 4277.27,3703.12 4277,3702.69 4276.71,3702.28 4276.39,3701.88 4275.67,3701.12 4273.58,3699.18
  region net LED5EN: 4773.14,4458.74 4783.74,4448.14 4785.75,4450.28 4786.5,4451.04 4786.88,4451.39 4787.28,4451.71 4787.69,4452 4788.12,4452.27 4788.58,4452.5 4789.07,4452.69 4789.59,4452.84 4790.15,4452.95 4790.75,4453.02 4778.02,4465.75 4777.95,4465.15 4777.84,4464.59 4777.69,4464.07 4777.5,4463.58 4777.27,4463.12 4777,4462.69 4776.71,4462.28 4776.39,4461.88 4775.67,4461.12 4773.58,4459.18
  region net LED6EN: 4773.14,3698.74 4783.74,3688.14 4785.75,3690.28 4786.5,3691.04 4786.88,3691.39 4787.28,3691.71 4787.69,3692 4788.12,3692.27 4788.58,3692.5 4789.07,3692.69 4789.59,3692.84 4790.15,3692.95 4790.75,3693.02 4778.02,3705.75 4777.95,3705.15 4777.84,3704.59 4777.69,3704.07 4777.5,3703.58 4777.27,3703.12 4777,3702.69 4776.71,3702.28 4776.39,3701.88 4775.67,3701.12 4773.58,3699.18
  region net LED7EN: 5273.14,4458.74 5283.74,4448.14 5285.75,4450.28 5286.5,4451.04 5286.88,4451.39 5287.28,4451.71 5287.69,4452 5288.12,4452.27 5288.58,4452.5 5289.07,4452.69 5289.59,4452.84 5290.15,4452.95 5290.75,4453.02 5278.02,4465.75 5277.95,4465.15 5277.84,4464.59 5277.69,4464.07 5277.5,4463.58 5277.27,4463.12 5277,4462.69 5276.71,4462.28 5276.39,4461.88 5275.67,4461.12 5273.58,4459.18
  region net LED8EN: 5273.14,3698.74 5283.74,3688.14 5285.75,3690.28 5286.5,3691.04 5286.88,3691.39 5287.28,3691.71 5287.69,3692 5288.12,3692.27 5288.58,3692.5 5289.07,3692.69 5289.59,3692.84 5290.15,3692.95 5290.75,3693.02 5278.02,3705.75 5277.95,3705.15 5277.84,3704.59 5277.69,3704.07 5277.5,3703.58 5277.27,3703.12 5277,3702.69 5276.71,3702.28 5276.39,3701.88 5275.67,3701.12 5273.58,3699.18
  region net LED6+: 4786.21,4806.36 4837.43,4840 ccw(c4732.06,4734.63) 4795,4869.7 4765.3,4840 ccw(c4847.85,4868)

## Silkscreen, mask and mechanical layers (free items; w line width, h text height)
Top Silkscreen Layer:
  text "LED1+" at 4249.99,4850.06 h29.2 r270
  text "LED2+" at 4349.99,4850.06 h29.2 r270
  text "LED3+" at 4449.99,4850.06 h29.2 r270
  text "LED4+" at 4549.99,4850.06 h29.2 r270
  text "LED5+" at 4649.99,4850.06 h29.2 r270
  text "LED6+" at 4749.99,4850.06 h29.2 r270
  text "LED7+" at 4849.99,4850.06 h29.2 r270
  text "LED8+" at 4949.99,4850.06 h29.2 r270
  text "5V" at 3299.99,4186.21 h29.2 r270
  text "GND" at 3299.99,3712.49 h29.2 r270
  text "LED1EN" at 4285.01,3218.66 h29.2 r90
  text "LED2EN" at 4385.01,3218.66 h29.2 r90
  text "LED3EN" at 4485.01,3218.66 h29.2 r90
  text "LED4EN" at 4585.01,3218.66 h29.2 r90
  text "LED5EN" at 4685.01,3218.66 h29.2 r90
  text "LED6EN" at 4785.01,3218.66 h29.2 r90
  text "LED7EN" at 4885.01,3218.66 h29.2 r90
  text "LED8EN" at 4985.01,3218.66 h29.2 r90
Mechanical Layer:
  circle w1 net "": c3330,4990 r59.06
  circle w1 net "": c5630,4990 r59.06
  circle w1 net "": c3330,3190 r59.06
  circle w1 net "": c5630,3190 r59.06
